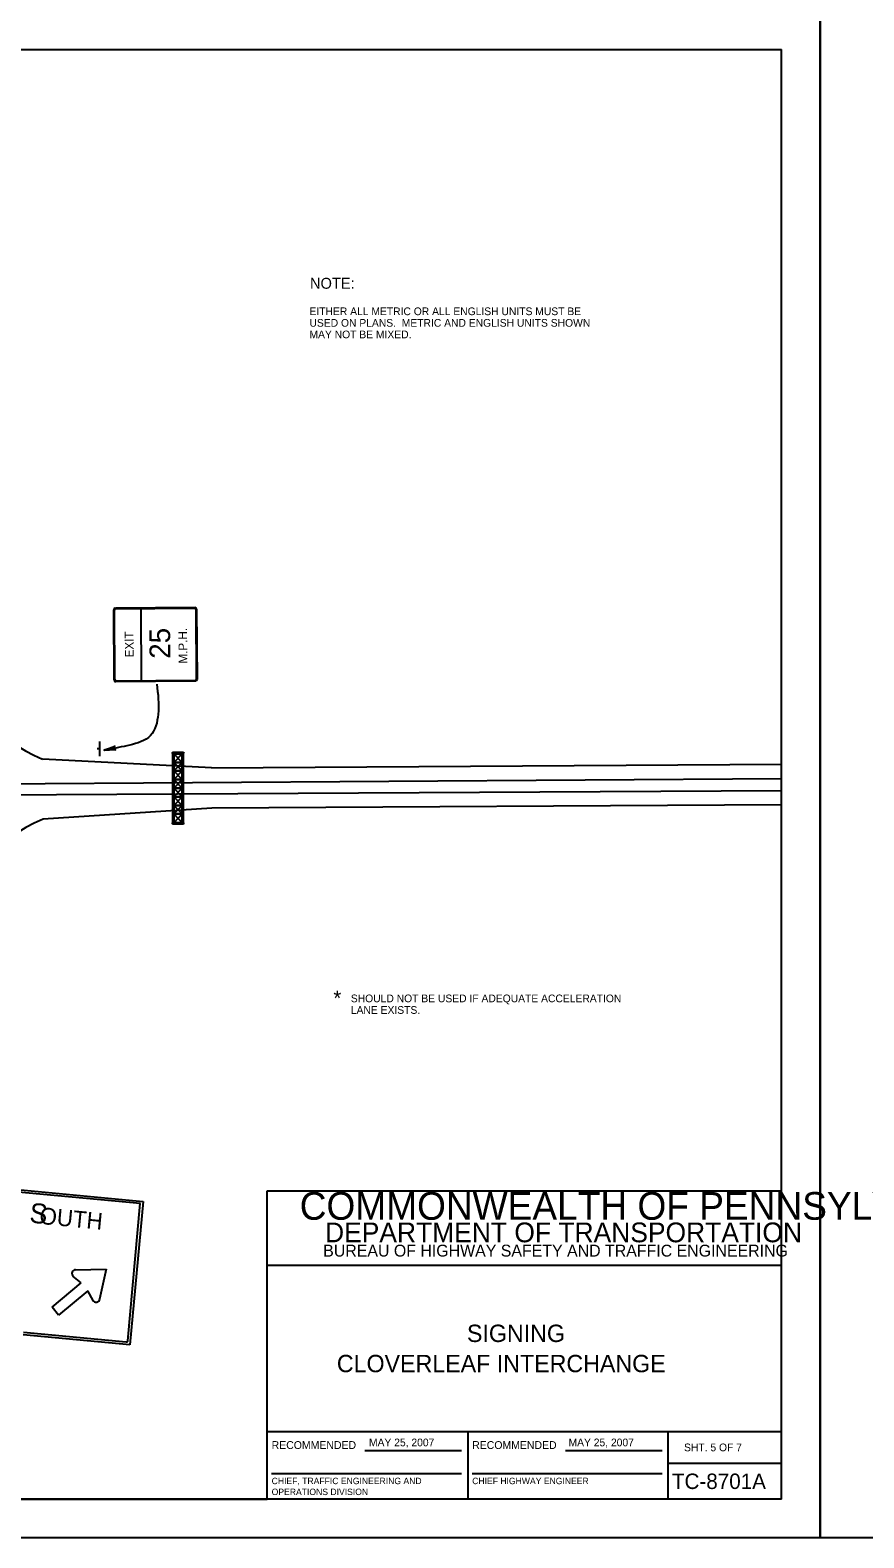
# Model space of a CAD drawing. Extents: x 640994 to 644422, y 298458 to 299646.
# Drawn here: x 641528 to 641852, y 298458 to 299044 of the extents above; entities that cross this region are included whole.
import ezdxf

# ---------------------------------------------------------------- set-up
doc = ezdxf.new("R2010")
doc.units = 0
for name, color, linetype in [('1', 7, 'Continuous'), ('2', 7, 'Continuous'), ('XCS-GRID-MIN', 7, 'Continuous')]:
    doc.layers.add(name, color=color, linetype=linetype)

msp = doc.modelspace()

# ---------------------------------------------------------------- linework, layer by layer
at = {"layer": '1'}
for p, q in [((641034.31, 299036.63), (641820.31, 299036.63)), ((641820.31, 298472.63), (641820.31, 299036.63)), ((641620.31, 298472.63), (641620.31, 298592.63)), ((641620.31, 298592.63), (641820.31, 298592.63)), ((641820.31, 298563.63), (641620.31, 298563.63)), ((641620.31, 298499), (641820.31, 298499)), ((641698.31, 298499), (641698.31, 298472.63)), ((641776.19, 298472.63), (641776.19, 298499)), ((641658.24, 298491.57), (641695.87, 298491.57)), ((641736.24, 298491.57), (641773.87, 298491.57)), ((641621.99, 298482.68), (641695.87, 298482.68)), ((641699.99, 298482.68), (641773.87, 298482.68)), ((641776.19, 298486.63), (641820.31, 298486.63)), ((641820.31, 298472.63), (641034.31, 298472.63)), ((641034.31, 298472.63), (641620.31, 298472.63))]:
    msp.add_line(p, q, dxfattribs=at)
at = {"layer": '2'}
for p, q in [((641560.69, 298791.38), (641560.56, 298818.63)), ((641560.94, 298791.5), (641560.81, 298818.38)), ((641561.19, 298819.38), (641592.19, 298819.63)), ((641561.31, 298819), (641591.94, 298819.25)), ((641571.31, 298791), (641571.19, 298819.13)), ((641592.56, 298818.63), (641592.69, 298791.75)), ((641592.81, 298818.88), (641593.06, 298791.5)), ((641592.44, 298790.88), (641561.31, 298790.63)), ((641592.19, 298791.13), (641561.56, 298790.88)), ((641555.06, 298764.5), (641554.06, 298764.5)), ((641555.06, 298767.38), (641555.06, 298761.75)), ((641598.56, 298757.13), (641532.94, 298760.5)), ((641583.94, 298762.63), (641587.19, 298759.25)), ((641587.19, 298762.63), (641583.94, 298759.25)), ((641583.94, 298759.25), (641587.19, 298756)), ((641587.19, 298759.25), (641583.94, 298756)), ((641598.56, 298757.13), (641820.31, 298758.53)), ((641820.31, 298752.92), (641403.56, 298750.13)), ((641583.94, 298756), (641587.19, 298752.63)), ((641587.19, 298756), (641583.94, 298752.63)), ((641583.94, 298752.63), (641587.19, 298749.25)), ((641587.19, 298752.63), (641583.94, 298749.25)), ((641403.06, 298746), (641820.31, 298748.39)), ((641583.94, 298749.25), (641587.19, 298745.88)), ((641587.19, 298749.25), (641583.94, 298745.88)), ((641583.94, 298745.88), (641587.19, 298742.5)), ((641587.19, 298745.88), (641583.94, 298742.5)), ((641598.69, 298741.5), (641533.06, 298737.25)), ((641583.94, 298742.5), (641587.19, 298739.25)), ((641587.19, 298742.5), (641583.94, 298739.25)), ((641820.31, 298742.77), (641598.69, 298741.5)), ((641583.94, 298739.25), (641587.19, 298735.75)), ((641587.19, 298739.25), (641583.94, 298735.75)), ((641587.19, 298735.75), (641587.19, 298739.25)), ((641482.95, 298596.91), (641572.07, 298588.42)), ((641566.07, 298534.29), (641570.89, 298587.75)), ((641572.07, 298588.42), (641566.82, 298532.67)), ((641547.95, 298556.79), (641544.7, 298559.42)), ((641545.7, 298561.92), (641557.57, 298562.17)), ((641557.57, 298562.17), (641555.07, 298550.42)), ((641536.57, 298547.42), (641547.95, 298556.79)), ((641550.45, 298553.67), (641539.07, 298544.29)), ((641552.57, 298549.92), (641550.45, 298553.67)), ((641539.07, 298544.29), (641536.57, 298547.42)), ((641566.82, 298532.67), (641525.37, 298536.61)), ((641525.47, 298537.63), (641565.45, 298533.92))]:
    msp.add_line(p, q, dxfattribs=at)
for points in [[(641561.03, 298764.34), (641560.78, 298764.59), (641556.9, 298764.09), (641561.03, 298764.34), (641561.28, 298764.21), (641556.9, 298764.09), (641560.78, 298764.96), (641560.78, 298765.21), (641556.9, 298764.09), (641561.03, 298765.59), (641560.78, 298765.21)], [(641587.19, 298763.13), (641583.94, 298763.13)], [(641583.44, 298762.63), (641583.44, 298735.75)], [(641583.94, 298735.75), (641587.19, 298735.75), (641587.19, 298762.63), (641583.94, 298762.63), (641583.94, 298735.75)], [(641587.69, 298735.75), (641587.69, 298762.63)], [(641583.94, 298735.38), (641587.19, 298735.38)], [(641570.89, 298587.75), (641484.32, 298595.67)]]:
    msp.add_lwpolyline(points, dxfattribs=at)
for points in [[(641583.94, 298759.25), (641583.94, 298762.63), (641587.19, 298762.63), (641587.19, 298759.25)], [(641583.94, 298756), (641583.94, 298759.25), (641587.19, 298759.25), (641587.19, 298756)], [(641583.94, 298752.63), (641583.94, 298756), (641587.19, 298756), (641587.19, 298752.63)], [(641583.94, 298749.25), (641583.94, 298752.63), (641587.19, 298752.63), (641587.19, 298749.25)], [(641583.94, 298745.88), (641583.94, 298749.25), (641587.19, 298749.25), (641587.19, 298745.88)], [(641583.94, 298742.5), (641583.94, 298745.88), (641587.19, 298745.88), (641587.19, 298742.5)], [(641583.94, 298739.25), (641583.94, 298742.5), (641587.19, 298742.5), (641587.19, 298739.25)], [(641583.94, 298735.75), (641583.94, 298739.25), (641587.19, 298739.25), (641587.19, 298735.75)]]:
    msp.add_lwpolyline(points, close=True, dxfattribs=at)
for centre in [(641583.7, 298762.91), (641587.48, 298762.91), (641583.7, 298735.61), (641587.48, 298735.61)]:
    msp.add_circle(centre, 0.301, dxfattribs=at)
for centre, radius, start, end in [((641555.3, 298815.87), 59.66, 191.54204, 247.96006), ((641556.17, 298682.23), 59.66, 112.7883, 169.20632), ((641570.38, 298587.12), 0.528, 354.14399, 84.50768), ((641545.72, 298560.49), 1.4, 89.42516, 230.09068), ((641553.72, 298550.69), 1.4, 207.81363, 351.72026), ((641565.52, 298534.36), 0.528, 264.80557, 354.95755)]:
    msp.add_arc(centre, radius, start, end, dxfattribs=at)
for centre, major_axis, start_param, end_param in [((641561.19, 298818.62), (0.005, -0.717), 3.141593, 4.712389), ((641561.38, 298818.41), (0.004, -0.657), 3.141593, 4.712389), ((641591.98, 298818.61), (-0.004, 0.657), 4.712389, 6.283185), ((641592.17, 298818.82), (-0.005, 0.717), 4.712389, 6.283185), ((641561.37, 298791.37), (0.005, -0.717), 4.712389, 6.283185), ((641561.56, 298791.58), (0.004, -0.657), 4.712389, 6.283185), ((641592.15, 298791.78), (-0.004, 0.657), 3.141593, 4.712389), ((641592.34, 298791.58), (0.005, -0.717), 0, 1.570796)]:
    msp.add_ellipse(centre, major_axis=major_axis, ratio=0.9, start_param=start_param, end_param=end_param, dxfattribs=at)
msp.add_spline([(641577.3, 298789.76), (641577.85, 298777.96), (641574.82, 298769.72), (641566.77, 298766), (641558.15, 298764.3)], degree=3, dxfattribs=at)
at = {"layer": 'XCS-GRID-MIN'}
for points in [[(640994.31, 299051.63), (641835.31, 299051.63), (641835.31, 298457.63), (640994.31, 298457.63)], [(641835.31, 299051.63), (642676.31, 299051.63), (642676.31, 298457.63), (641835.31, 298457.63)]]:
    msp.add_lwpolyline(points, close=True, dxfattribs=at)

# ---------------------------------------------------------------- texts
at = {"layer": '1'}
for s, height, p in [('COMMONWEALTH OF PENNSYLVANIA', 10.7828, (641632.9, 298581.36)), ('DEPARTMENT OF TRANSPORTATION', 7.6837, (641642.76, 298572.61)), ('BUREAU OF HIGHWAY SAFETY AND TRAFFIC ENGINEERING', 4.6253, (641642.04, 298567.04)), ('SIGNING', 6.75, (641697.96, 298533.81)), ('CLOVERLEAF INTERCHANGE', 6.75, (641647.36, 298522.06)), ('RECOMMENDED', 3.048, (641621.99, 298492.2)), ('RECOMMENDED', 3.048, (641699.99, 298492.2)), ('SHT. 5 OF 7', 3, (641782.4, 298491.31)), ('TC-8701A', 6, (641777.68, 298476.63)), ('OPERATIONS DIVISION', 2.5, (641621.99, 298474.26)), ('CHIEF, TRAFFIC ENGINEERING AND', 2.5, (641621.99, 298478.51)), ('CHIEF HIGHWAY ENGINEER', 2.5, (641699.99, 298478.51))]:
    msp.add_text(s, height=height, dxfattribs=at).set_placement(p)
at = {"layer": '2'}
for s, height, p in [('NOTE:', 4.25, (641636.91, 298943.53)), ('EITHER ALL METRIC OR ALL ENGLISH UNITS MUST BE', 3, (641636.7, 298933.26)), ('USED ON PLANS.  METRIC AND ENGLISH UNITS SHOWN', 3, (641636.7, 298928.76)), ('MAY NOT BE MIXED.', 3, (641636.7, 298924.26)), ('*', 5.85, (641646.02, 298664.66)), ('SHOULD NOT BE USED IF ADEQUATE ACCELERATION', 3, (641652.79, 298665.97)), ('LANE EXISTS.', 3, (641652.79, 298661.47)), ('MAY 25, 2007', 3, (641659.85, 298493.24))]:
    msp.add_text(s, height=height, dxfattribs=at).set_placement(p)
for s, height, rotation, p in [('EXIT', 3.387, 90.3745, (641568.31, 298800.13)), ('25', 8.061, 90.37458, (641582.56, 298799.63)), ('M.P.H.', 3.387, 90.37456, (641589.19, 298797.75)), ('35', 0.0217, 90, (641572.56, 298800.88)), ('S', 7.75, 354.58165, (641527.57, 298580.29)), ('OUTH', 6.5, 354.56831, (641531.45, 298579.79)), ('MAY 25, 2007', 3, 360, (641737.47, 298493.24))]:
    msp.add_text(s, height=height, rotation=rotation, dxfattribs=at).set_placement(p)

doc.saveas('drawing.dxf')
